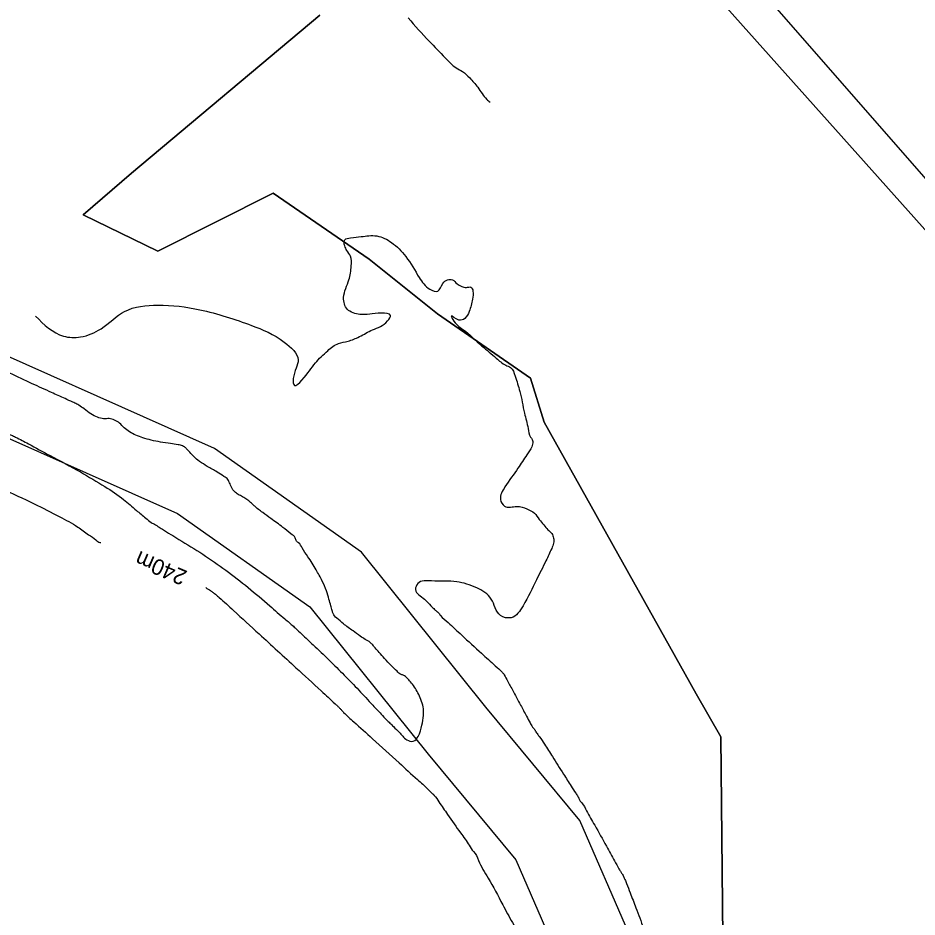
# Model space of a CAD drawing. Extents: x -478495 to -472450, y -1118050 to -1113745.
# Drawn here: x -476696.5 to -476594.3, y -1115480.3 to -1115378.2 of the extents above; entities that cross this region are included whole.
import ezdxf

# ---------------------------------------------------------------- set-up
doc = ezdxf.new("R2010")
doc.units = 0
for name, color, linetype in [('cyklostezka', 7, 'Continuous'), ('ObPÚ', 7, 'Continuous'), ('silnice', 7, 'Continuous'), ('vodní plochy', 7, 'Continuous'), ('Vrstevnice_hlavni', 7, 'Continuous'), ('Vrstevnice_popis', 7, 'Continuous'), ('Vrstevnice_vedlejsi', 7, 'Continuous')]:
    doc.layers.add(name, color=color, linetype=linetype)

msp = doc.modelspace()

# ---------------------------------------------------------------- linework, layer by layer
at = {"layer": 'cyklostezka'}
msp.add_lwpolyline([(-477033.5754190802, -1115019.3150603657), (-476978.4562666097, -1115069.8432601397), (-476859.56050309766, -1115163.970078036), (-476838.56618741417, -1115180.4272610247), (-476823.49769734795, -1115192.2844335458), (-476742.0352354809, -1115258.9995421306), (-476654.0177406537, -1115335.224940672), (-476615.8651919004, -1115370.6739552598), (-476567.0504242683, -1115426.523456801)], dxfattribs=at)
at = {"layer": 'ObPÚ'}
for p, q in [((-476662.2074801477, -1115377.8477040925), (-476683.6261630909, -1115395.7950832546)), ((-476683.6261630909, -1115395.7950832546), (-476662.2074801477, -1115377.8477040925)), ((-476683.6261630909, -1115395.7950832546), (-476689.09162010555, -1115400.5219649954)), ((-476689.09162010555, -1115400.5219649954), (-476683.6261630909, -1115395.7950832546)), ((-476680.5980044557, -1115404.6579865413), (-476667.52522211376, -1115398.0846665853)), ((-476667.52522211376, -1115398.0846665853), (-476680.5980044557, -1115404.6579865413)), ((-476667.52522211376, -1115398.0846665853), (-476656.5858514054, -1115405.5557986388)), ((-476656.5858514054, -1115405.5557986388), (-476667.52522211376, -1115398.0846665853)), ((-476689.09162010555, -1115400.5219649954), (-476680.5980044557, -1115404.6579865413)), ((-476680.5980044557, -1115404.6579865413), (-476689.09162010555, -1115400.5219649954)), ((-476656.5858514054, -1115405.5557986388), (-476648.83081102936, -1115411.7598309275)), ((-476648.83081102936, -1115411.7598309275), (-476656.5858514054, -1115405.5557986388)), ((-476648.83081102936, -1115411.7598309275), (-476638.2691846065, -1115419.0717261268)), ((-476638.2691846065, -1115419.0717261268), (-476648.83081102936, -1115411.7598309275)), ((-476638.2691846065, -1115419.0717261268), (-476636.7181765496, -1115424.0940379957)), ((-476636.7181765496, -1115424.0940379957), (-476638.2691846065, -1115419.0717261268)), ((-476636.7181765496, -1115424.0940379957), (-476619.43551515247, -1115454.9664844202)), ((-476619.43551515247, -1115454.9664844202), (-476636.7181765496, -1115424.0940379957)), ((-476619.43551515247, -1115454.9664844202), (-476616.6289291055, -1115459.8410812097)), ((-476616.6289291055, -1115459.8410812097), (-476619.43551515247, -1115454.9664844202)), ((-476616.6289291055, -1115459.8410812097), (-476616.2596414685, -1115498.6901405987)), ((-476616.2596414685, -1115498.6901405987), (-476616.6289291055, -1115459.8410812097))]:
    msp.add_line(p, q, dxfattribs=at)
at = {"layer": 'silnice'}
msp.add_lwpolyline([(-476200.5430969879, -1116268.1533225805), (-476239.9646638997, -1116179.1988064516), (-476260.9335824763, -1116109.5457419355), (-476288.6125549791, -1116007.1641290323), (-476289.4513117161, -1115970.2396129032), (-476274.35369035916, -1115930.797516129), (-476257.5785554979, -1115904.782516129), (-476369.13277385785, -1115816.6670000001), (-476386.7466654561, -1115803.239903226), (-476421.13569191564, -1115718.4813548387), (-476492.4300150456, -1115557.3561935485), (-476531.85169606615, -1115480.150387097), (-476576.30580343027, -1115421.4068387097), (-476632.5025051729, -1115358.4673225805), (-476738.18585476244, -1115266.156032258), (-476821.72644138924, -1115198.097580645), (-476986.4582147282, -1115072.218548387), (-477038.7966192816, -1115021.8669354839), (-477039.4315830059, -1115021.0219319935)], dxfattribs=at)
at = {"layer": 'vodní plochy'}
for points in [[(-476627.07755504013, -1115482.1470422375), (-476632.6667913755, -1115469.3284741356), (-476643.33627759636, -1115456.469906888), (-476657.4842331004, -1115438.8651223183), (-476674.1718304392, -1115427.0631315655), (-476706.13880376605, -1115412.850244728), (-476729.98436298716, -1115399.7600339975), (-476740.4879913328, -1115387.341275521), (-476748.6894797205, -1115366.3950057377), (-476759.92400238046, -1115343.4554805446), (-476770.8296953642, -1115321.4005905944), (-476783.5129779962, -1115303.0978776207), (-476802.0099790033, -1115286.6187305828), (-476817.2501663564, -1115274.8740825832), (-476841.610815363, -1115265.5770420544), (-476863.5968128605, -1115264.5539054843), (-476890.1958391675, -1115270.8442189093), (-476915.2418181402, -1115280.6291652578), (-476937.4833280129, -1115294.7062318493), (-476976.86007675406, -1115325.552483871), (-477001.1458366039, -1115336.1103548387), (-477017.8542173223, -1115334.32174456), (-477032.5618690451, -1115330.3446355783), (-477069.62774202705, -1115314.5480858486)], [(-477073.4151823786, -1115322.1289234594), (-477035.3374001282, -1115338.356723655), (-477018.62148490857, -1115342.8768889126), (-477000.337994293, -1115343.9908709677), (-476973.1238060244, -1115331.2608064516), (-476932.7643093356, -1115301.73017597), (-476911.40568257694, -1115288.211902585), (-476887.6710396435, -1115278.939268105), (-476862.80478527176, -1115273.0587320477), (-476843.35930301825, -1115273.9636436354), (-476821.4282958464, -1115282.3334314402), (-476807.41192132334, -1115293.1349643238), (-476789.891888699, -1115308.743721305), (-476778.13651078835, -1115325.707413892), (-476767.51361061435, -1115347.1904040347), (-476756.4391938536, -1115369.8030124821), (-476747.8528420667, -1115391.7322078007), (-476735.4299142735, -1115406.4202122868), (-476709.8989106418, -1115420.4356612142), (-476678.3729412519, -1115434.452472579), (-476663.33566597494, -1115445.0873039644), (-476649.8882640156, -1115461.820365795), (-476639.9416470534, -1115473.8077512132), (-476635.30298632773, -1115484.4462328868)]]:
    msp.add_lwpolyline(points, dxfattribs=at)
at = {"layer": 'Vrstevnice_hlavni'}
for points in [[(-476694.514, -1115412.045), (-476691.34500000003, -1115414.305), (-476689.393, -1115414.404), (-476687.074, -1115413.4710000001), (-476684.386, -1115411.507), (-476680.639, -1115410.789), (-476675.832, -1115411.318), (-476669.965, -1115413.094), (-476666.242, -1115414.989), (-476664.663, -1115417.004), (-476665.227, -1115419.137), (-476665.08900000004, -1115419.9070000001), (-476664.248, -1115419.314), (-476662.704, -1115417.357), (-476661.315, -1115415.966), (-476660.082, -1115415.141), (-476659.004, -1115414.882), (-476657.715, -1115414.37), (-476656.21400000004, -1115413.6030000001), (-476654.50200000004, -1115412.584), (-476654.173, -1115411.949), (-476655.227, -1115411.7), (-476657.66500000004, -1115411.8360000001), (-476659.08900000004, -1115411.249), (-476659.5, -1115409.939), (-476658.898, -1115407.906), (-476658.635, -1115406.3360000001), (-476658.712, -1115405.23), (-476659.128, -1115404.587), (-476659.376, -1115404.062), (-476659.454, -1115403.656), (-476659.363, -1115403.369), (-476658.713, -1115403.152), (-476657.505, -1115403.0050000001), (-476655.737, -1115402.929), (-476654.049, -1115403.68), (-476652.439, -1115405.258), (-476650.909, -1115407.664), (-476649.699, -1115408.979), (-476648.811, -1115409.202), (-476648.243, -1115408.335), (-476647.68700000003, -1115407.906), (-476647.14400000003, -1115407.9170000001), (-476646.613, -1115408.367), (-476646.085, -1115408.656), (-476645.559, -1115408.783), (-476645.036, -1115408.749), (-476644.80700000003, -1115409.192), (-476644.871, -1115410.112), (-476645.229, -1115411.508), (-476645.74700000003, -1115412.298), (-476646.42600000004, -1115412.48), (-476647.265, -1115412.055), (-476647.104, -1115412.408), (-476645.942, -1115413.539), (-476643.78, -1115415.447), (-476642.16000000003, -1115416.803), (-476641.083, -1115417.608), (-476640.548, -1115417.86), (-476640.014, -1115418.854), (-476639.481, -1115420.589), (-476638.949, -1115423.066), (-476638.54000000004, -1115424.799), (-476638.253, -1115425.79), (-476638.09, -1115426.037), (-476638.01300000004, -1115426.299), (-476638.023, -1115426.577), (-476638.119, -1115426.871), (-476638.67600000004, -1115427.78), (-476639.692, -1115429.303), (-476641.169, -1115431.442), (-476641.68, -1115432.882), (-476641.226, -1115433.6230000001), (-476639.806, -1115433.6670000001), (-476638.674, -1115433.9340000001), (-476637.83, -1115434.426), (-476637.273, -1115435.142), (-476636.759, -1115435.768), (-476636.288, -1115436.304), (-476635.858, -1115436.75), (-476635.64400000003, -1115437.2550000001), (-476635.645, -1115437.82), (-476635.862, -1115438.443), (-476636.512, -1115439.842), (-476637.596, -1115442.0150000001), (-476639.114, -1115444.962), (-476640.476, -1115446.306), (-476641.681, -1115446.046), (-476642.729, -1115444.182), (-476644.38300000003, -1115442.9070000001), (-476646.642, -1115442.22), (-476649.507, -1115442.122), (-476651.07300000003, -1115442.418), (-476651.342, -1115443.108), (-476650.314, -1115444.192), (-476649.587, -1115444.95), (-476649.162, -1115445.383)], [(-476717.286, -1115421.538), (-476717.213, -1115421.575), (-476716.913, -1115421.725), (-476716.385, -1115421.989), (-476715.629, -1115422.367), (-476714.01900000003, -1115423.251), (-476711.555, -1115424.642), (-476708.23600000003, -1115426.539), (-476705.712, -1115427.96), (-476703.983, -1115428.9070000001), (-476703.047, -1115429.378), (-476701.18200000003, -1115430.278), (-476698.387, -1115431.607), (-476694.663, -1115433.365), (-476691.771, -1115434.829), (-476689.711, -1115436), (-476688.482, -1115436.876), (-476687.64400000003, -1115437.463), (-476687.195, -1115437.758), (-476687.077, -1115437.769)], [(-476675.172, -1115442.891), (-476674.626, -1115443.23), (-476674.326, -1115443.4440000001), (-476673.998, -1115443.703), (-476673.643, -1115444.006), (-476672.012, -1115445.487), (-476669.106, -1115448.147), (-476664.923, -1115451.985), (-476662.048, -1115454.626), (-476660.479, -1115456.072), (-476660.217, -1115456.321), (-476659.967, -1115456.568), (-476659.729, -1115456.815), (-476659.50200000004, -1115457.0590000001), (-476658.33900000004, -1115458.137), (-476656.24, -1115460.049), (-476653.205, -1115462.795), (-476651.104, -1115464.702), (-476649.939, -1115465.77), (-476649.71, -1115466), (-476649.538, -1115466.17), (-476649.425, -1115466.28), (-476649.37, -1115466.33), (-476649.316, -1115466.382), (-476649.261, -1115466.437), (-476649.207, -1115466.495), (-476648.681, -1115467.234), (-476647.683, -1115468.656), (-476646.21400000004, -1115470.761), (-476645.234, -1115472.165), (-476644.744, -1115472.867), (-476644.743, -1115472.868), (-476644.742, -1115472.869), (-476644.74100000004, -1115472.87), (-476644.189, -1115473.878), (-476643.085, -1115475.892), (-476641.429, -1115478.913), (-476640.313, -1115480.954), (-476639.73600000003, -1115482.014), (-476639.7, -1115482.095), (-476639.658, -1115482.232), (-476639.61, -1115482.426), (-476639.555, -1115482.676), (-476639.518, -1115482.842), (-476639.5, -1115482.925), (-476639.501, -1115482.924), (-476639.378, -1115483.565), (-476639.13300000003, -1115484.8460000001), (-476638.766, -1115486.769), (-476638.40400000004, -1115488.387), (-476638.048, -1115489.699), (-476637.69800000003, -1115490.706), (-476637.354, -1115491.828), (-476637.017, -1115493.063), (-476636.686, -1115494.413), (-476636.484, -1115495.376), (-476636.411, -1115495.954), (-476636.467, -1115496.145), (-476636.54600000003, -1115496.4980000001), (-476636.648, -1115497.014), (-476636.772, -1115497.691), (-476636.911, -1115498.298), (-476637.064, -1115498.8360000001), (-476637.232, -1115499.305), (-476637.332, -1115499.8800000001), (-476637.364, -1115500.562), (-476637.32800000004, -1115501.351), (-476637.305, -1115501.916), (-476637.295, -1115502.2550000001), (-476637.299, -1115502.369), (-476637.302, -1115502.476), (-476637.305, -1115502.575), (-476637.308, -1115502.666), (-476637.314, -1115502.785), (-476637.32300000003, -1115502.931), (-476637.335, -1115503.105), (-476637.185, -1115503.279), (-476636.871, -1115503.453), (-476636.395, -1115503.627), (-476635.985, -1115503.7), (-476635.641, -1115503.673), (-476635.364, -1115503.545), (-476635.163, -1115503.629), (-476635.036, -1115503.926), (-476634.985, -1115504.435), (-476634.924, -1115505.348), (-476634.853, -1115506.665), (-476634.773, -1115508.386), (-476634.73, -1115509.857), (-476634.72500000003, -1115511.078), (-476634.757, -1115512.048), (-476634.794, -1115512.909), (-476634.835, -1115513.661), (-476634.88, -1115514.304), (-476634.98600000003, -1115514.959), (-476635.152, -1115515.626)], [(-476649.162, -1115445.383), (-476649.04000000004, -1115445.49), (-476648.941, -1115445.572), (-476648.865, -1115445.628), (-476648.813, -1115445.658), (-476648.733, -1115445.739), (-476648.624, -1115445.87), (-476648.485, -1115446.051), (-476647.64, -1115446.857), (-476646.086, -1115448.29), (-476643.825, -1115450.347), (-476642.282, -1115451.76), (-476641.45900000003, -1115452.527), (-476641.355, -1115452.649), (-476640.97500000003, -1115453.3090000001), (-476640.32, -1115454.508), (-476639.39, -1115456.245), (-476638.72500000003, -1115457.487), (-476638.325, -1115458.232), (-476638.189, -1115458.482), (-476638.072, -1115458.678), (-476637.972, -1115458.818), (-476637.89, -1115458.904), (-476637.818, -1115458.9980000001), (-476637.755, -1115459.099), (-476637.701, -1115459.209), (-476637.598, -1115459.369), (-476637.444, -1115459.58), (-476637.24100000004, -1115459.842), (-476636.68700000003, -1115460.676), (-476635.784, -1115462.084), (-476634.52900000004, -1115464.064), (-476633.647, -1115465.448), (-476633.135, -1115466.236), (-476632.994, -1115466.428), (-476632.881, -1115466.609), (-476632.795, -1115466.779), (-476632.737, -1115466.94), (-476632.656, -1115467.089), (-476632.553, -1115467.2280000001), (-476632.427, -1115467.356), (-476631.9, -1115468.24), (-476630.973, -1115469.8800000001), (-476629.645, -1115472.275), (-476628.72500000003, -1115473.931), (-476628.212, -1115474.8460000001), (-476628.107, -1115475.022), (-476628.006, -1115475.185), (-476627.909, -1115475.337), (-476627.816, -1115475.477), (-476627.693, -1115475.718), (-476627.539, -1115476.06), (-476627.355, -1115476.503), (-476626.941, -1115477.57), (-476626.298, -1115479.261), (-476625.42600000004, -1115481.577), (-476624.826, -1115483.283), (-476624.499, -1115484.379), (-476624.444, -1115484.865), (-476624.364, -1115485.358), (-476624.256, -1115485.859), (-476624.123, -1115486.367), (-476623.9, -1115487.607), (-476623.587, -1115489.58), (-476623.185, -1115492.284), (-476622.903, -1115494.208), (-476622.739, -1115495.352), (-476622.695, -1115495.716), (-476622.601, -1115496.605), (-476622.457, -1115498.019), (-476622.264, -1115499.957), (-476622.11100000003, -1115501.4170000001), (-476622, -1115502.399), (-476621.93, -1115502.903), (-476621.882, -1115503.325), (-476621.857, -1115503.666), (-476621.854, -1115503.924), (-476621.783, -1115505.089), (-476621.64400000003, -1115507.16), (-476621.43700000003, -1115510.137), (-476621.299, -1115512.128), (-476621.23, -1115513.132), (-476621.229, -1115513.166)]]:
    msp.add_spline(points, degree=3, dxfattribs=at)
at = {"layer": 'Vrstevnice_vedlejsi'}
for points in [[(-476782.237, -1115320.1230000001), (-476781.89400000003, -1115320.658), (-476781.575, -1115321.206), (-476781.278, -1115321.766), (-476781.004, -1115322.338), (-476780.51900000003, -1115323.233), (-476779.82300000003, -1115324.45), (-476778.917, -1115325.991), (-476778.088, -1115327.415), (-476777.337, -1115328.722), (-476776.664, -1115329.912), (-476776.033, -1115330.843), (-476775.445, -1115331.514), (-476774.901, -1115331.926), (-476774.298, -1115332.797), (-476773.63800000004, -1115334.125), (-476772.919, -1115335.911), (-476772.483, -1115337.259), (-476772.327, -1115338.168), (-476772.45300000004, -1115338.639), (-476772.442, -1115339.19), (-476772.295, -1115339.823), (-476772.01, -1115340.536), (-476771.63, -1115341.381), (-476771.15400000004, -1115342.357), (-476770.581, -1115343.464), (-476769.729, -1115345.262), (-476768.597, -1115347.752), (-476767.186, -1115350.932), (-476765.737, -1115354.067), (-476764.251, -1115357.156), (-476762.728, -1115360.2), (-476761.525, -1115362.664), (-476760.643, -1115364.548), (-476760.08, -1115365.851), (-476759.25200000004, -1115367.612), (-476758.157, -1115369.831), (-476756.797, -1115372.509), (-476755.717, -1115374.638), (-476754.918, -1115376.22), (-476754.4, -1115377.253), (-476753.686, -1115378.773), (-476752.77900000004, -1115380.777), (-476751.67600000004, -1115383.267), (-476750.604, -1115385.5690000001), (-476749.564, -1115387.683), (-476748.555, -1115389.609), (-476747.753, -1115391.107), (-476747.157, -1115392.176), (-476746.76900000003, -1115392.816), (-476745.549, -1115394.316), (-476743.499, -1115396.676), (-476740.618, -1115399.896), (-476738.554, -1115402.2010000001), (-476737.309, -1115403.591), (-476736.881, -1115404.066), (-476736.474, -1115404.475), (-476736.086, -1115404.817), (-476735.719, -1115405.094), (-476734.62700000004, -1115406.0690000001), (-476732.811, -1115407.743), (-476730.271, -1115410.116), (-476728.369, -1115411.818), (-476727.105, -1115412.85), (-476726.48, -1115413.21), (-476724.474, -1115414.254), (-476721.088, -1115415.982), (-476716.321, -1115418.392), (-476712.928, -1115420.107), (-476710.91000000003, -1115421.125), (-476710.266, -1115421.447), (-476708.515, -1115422.06), (-476705.659, -1115422.963), (-476701.696, -1115424.1570000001), (-476698.897, -1115425.025), (-476697.26, -1115425.566), (-476696.787, -1115425.7820000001), (-476695.322, -1115426.55), (-476692.86600000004, -1115427.871), (-476689.419, -1115429.745), (-476686.63300000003, -1115431.41), (-476684.509, -1115432.866), (-476683.045, -1115434.1130000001), (-476681.996, -1115434.986), (-476681.36100000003, -1115435.485), (-476681.14, -1115435.61), (-476680.092, -1115436.253), (-476678.218, -1115437.413), (-476675.517, -1115439.092), (-476672.896, -1115440.911), (-476670.354, -1115442.871), (-476667.892, -1115444.973), (-476666.18, -1115446.439), (-476665.218, -1115447.269), (-476665.006, -1115447.464), (-476664.259, -1115448.17), (-476662.978, -1115449.387)], [(-476692.696, -1115420.715), (-476694.882, -1115419.718), (-476697.418, -1115418.513), (-476700.305, -1115417.098), (-476703.542, -1115415.474), (-476705.90400000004, -1115414.291), (-476707.393, -1115413.548), (-476708.006, -1115413.245), (-476708.94, -1115412.7650000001), (-476710.195, -1115412.109), (-476711.76900000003, -1115411.277), (-476713.026, -1115410.593), (-476713.96400000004, -1115410.057), (-476714.58400000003, -1115409.67), (-476715.44, -1115409.145), (-476716.532, -1115408.483), (-476717.86, -1115407.685), (-476719.33900000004, -1115406.838), (-476720.967, -1115405.943), (-476722.746, -1115405), (-476724.11100000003, -1115404.266), (-476725.06200000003, -1115403.741), (-476725.598, -1115403.425), (-476726.21400000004, -1115403.111), (-476726.911, -1115402.798), (-476727.686, -1115402.486), (-476728.511, -1115401.948), (-476729.385, -1115401.185), (-476730.308, -1115400.195), (-476731.11, -1115399.36), (-476731.791, -1115398.678), (-476732.351, -1115398.151), (-476733.037, -1115397.46), (-476733.849, -1115396.605), (-476734.787, -1115395.585), (-476735.51900000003, -1115394.786), (-476736.04600000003, -1115394.208), (-476736.367, -1115393.85), (-476736.78500000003, -1115393.311), (-476737.30100000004, -1115392.59), (-476737.91500000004, -1115391.688), (-476738.479, -1115390.8800000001), (-476738.994, -1115390.1670000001), (-476739.46, -1115389.548), (-476739.969, -1115388.839), (-476740.521, -1115388.04), (-476741.11600000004, -1115387.15), (-476741.635, -1115386.268), (-476742.077, -1115385.393), (-476742.442, -1115384.525), (-476742.804, -1115383.666), (-476743.162, -1115382.817), (-476743.516, -1115381.976), (-476743.95300000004, -1115380.785), (-476744.471, -1115379.244), (-476745.072, -1115377.352), (-476745.543, -1115375.832), (-476745.886, -1115374.6840000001), (-476746.10000000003, -1115373.9070000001), (-476746.359, -1115373.068), (-476746.662, -1115372.1670000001), (-476747.011, -1115371.204), (-476747.337, -1115370.311), (-476747.641, -1115369.486), (-476747.923, -1115368.731), (-476748.294, -1115367.8730000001), (-476748.753, -1115366.912), (-476749.302, -1115365.848), (-476749.73600000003, -1115364.822), (-476750.055, -1115363.834), (-476750.26, -1115362.883), (-476750.46400000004, -1115362.104), (-476750.666, -1115361.495), (-476750.868, -1115361.057), (-476751.06200000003, -1115360.642), (-476751.248, -1115360.25), (-476751.427, -1115359.881), (-476751.825, -1115359.097), (-476752.443, -1115357.899), (-476753.281, -1115356.286), (-476754.152, -1115354.57), (-476755.055, -1115352.753), (-476755.992, -1115350.832), (-476756.788, -1115349.188), (-476757.443, -1115347.818), (-476757.957, -1115346.723), (-476758.618, -1115345.368), (-476759.425, -1115343.752), (-476760.38, -1115341.875), (-476760.999, -1115340.59), (-476761.283, -1115339.895), (-476761.231, -1115339.7920000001), (-476761.173, -1115339.655), (-476761.11100000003, -1115339.485), (-476761.043, -1115339.281), (-476761.08900000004, -1115339.081), (-476761.248, -1115338.885)], [(-476652.17600000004, -1115378.161), (-476649.791, -1115380.796), (-476647.966, -1115382.688), (-476646.7, -1115383.839), (-476645.994, -1115384.2480000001), (-476645.181, -1115384.9780000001), (-476644.261, -1115386.031), (-476643.233, -1115387.406), (-476642.8574428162, -1115387.7277300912)], [(-476662.978, -1115449.387), (-476661.162, -1115451.115), (-476659.428, -1115452.833), (-476657.775, -1115454.539), (-476656.20300000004, -1115456.234), (-476655.091, -1115457.422), (-476654.44, -1115458.1030000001), (-476654.248, -1115458.277), (-476653.83, -1115458.682), (-476653.188, -1115459.318), (-476652.32, -1115460.185), (-476651.602, -1115460.342), (-476651.034, -1115459.79), (-476650.61600000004, -1115458.529), (-476650.42600000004, -1115457.411), (-476650.465, -1115456.437), (-476650.734, -1115455.606), (-476651.064, -1115454.8530000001), (-476651.456, -1115454.179), (-476651.91000000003, -1115453.583), (-476652.314, -1115453.147), (-476652.667, -1115452.871), (-476652.971, -1115452.754), (-476653.438, -1115452.391), (-476654.067, -1115451.7820000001), (-476654.86, -1115450.927), (-476655.478, -1115450.245), (-476655.922, -1115449.736), (-476656.193, -1115449.4), (-476656.471, -1115449.126), (-476656.75800000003, -1115448.916), (-476657.052, -1115448.768), (-476657.61100000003, -1115448.399), (-476658.436, -1115447.8090000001), (-476659.525, -1115446.999), (-476660.283, -1115446.343), (-476660.70900000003, -1115445.841), (-476660.803, -1115445.493), (-476660.957, -1115444.947), (-476661.17100000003, -1115444.203), (-476661.444, -1115443.26), (-476661.933, -1115442.141), (-476662.639, -1115440.8460000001), (-476663.561, -1115439.375), (-476664.221, -1115438.364), (-476664.618, -1115437.813), (-476664.75200000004, -1115437.722), (-476664.86, -1115437.5960000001), (-476664.943, -1115437.4340000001), (-476665, -1115437.237), (-476665.492, -1115436.771), (-476666.419, -1115436.037), (-476667.78, -1115435.035), (-476668.702, -1115434.357), (-476669.185, -1115434.0050000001), (-476669.229, -1115433.9780000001), (-476669.39, -1115433.837), (-476669.67, -1115433.583), (-476670.069, -1115433.216), (-476670.505, -1115432.879), (-476670.978, -1115432.571), (-476671.488, -1115432.293), (-476671.875, -1115432.002), (-476672.139, -1115431.697), (-476672.28, -1115431.379), (-476672.413, -1115431.092), (-476672.539, -1115430.834), (-476672.658, -1115430.608), (-476673.107, -1115430.246), (-476673.887, -1115429.751), (-476674.998, -1115429.121), (-476675.882, -1115428.538), (-476676.537, -1115428.001), (-476676.965, -1115427.511), (-476677.317, -1115427.145), (-476677.594, -1115426.903), (-476677.795, -1115426.786), (-476678.319, -1115426.654), (-476679.16500000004, -1115426.506), (-476680.332, -1115426.344), (-476681.381, -1115426.133), (-476682.309, -1115425.874), (-476683.118, -1115425.567), (-476683.832, -1115425.1840000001), (-476684.45, -1115424.726), (-476684.974, -1115424.193), (-476685.537, -1115423.844), (-476686.14, -1115423.68), (-476686.782, -1115423.702), (-476687.474, -1115423.526), (-476688.215, -1115423.152), (-476689.005, -1115422.58), (-476689.612, -1115422.166), (-476690.034, -1115421.909), (-476690.272, -1115421.81), (-476691.16000000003, -1115421.412), (-476692.696, -1115420.715)]]:
    msp.add_spline(points, degree=3, dxfattribs=at)

# ---------------------------------------------------------------- texts
at = {"layer": 'Vrstevnice_popis'}
msp.add_text(' 240m ', height=1.8000000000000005, rotation=156.68695166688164, dxfattribs=at).set_placement((-476676.549, -1115441.311))

doc.saveas('drawing.dxf')
